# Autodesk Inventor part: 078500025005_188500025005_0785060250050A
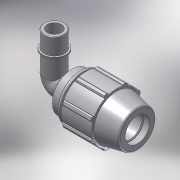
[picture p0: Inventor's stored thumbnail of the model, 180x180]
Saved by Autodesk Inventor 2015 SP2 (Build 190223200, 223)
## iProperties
Created: 2017-02
Part Number: 078500025005_188500025005_0785060250050A
Material: PVC-Piping
Description: PLASSON 90° ELBOW MALE ADAPTOR 25-1/2"
Document SubType Name: Modeling
Designer: KIM
Mass: 92.6774 g
Surface Area: 199.44 cm^2
Volume: 66.1981 cm^3
Density: 1.4 g/cm^3
Appearance: Smooth - White
Author: KIM
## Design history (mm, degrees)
derived "07850.ipt"
feature "Solid1::07850.ipt"
tag "TaggingFeature1"
body "Solid1"
other parameters: "d2" = 25, "d4" = 7.08333, "d5" = 21.25, "d7" = 54, "d9" = 12.14286, "d11" = 2.83333, "d13" = 120 deg, "d14" = 37.5, "d15" = 12 deg, "d16" = 46.98, "d18" = 1.25, "d19" = 35 deg, "d20" = 17.5 deg, "d21" = 50.22, "d23" = 0, "d25" = 360 deg, "d27" = 1.08, "d33" = 0.5, "d42" = 31.45, "d43" = 1.62, "d46" = 0.75, "d51" = 85, "d68" = 2.83333, "d72" = 47, "d73" = 20.955, "d74" = 17, "d75" = 24.09825, "d76" = 14.6685, "d77" = 18.7, "d79" = 8.382, "d80" = 0.62865, "d83" = 0, "d84" = 0, "d91" = 40.5, "d93" = 58, "d94" = 20.955, "d95" = 14.6685, "d96" = 8.5, "d97" = 50 deg, "d_" = 25, "E_" = 54, "A_" = 85, "l_" = 58, "l_2" = 17, "A_1" = 47, "R_" = 20.955
